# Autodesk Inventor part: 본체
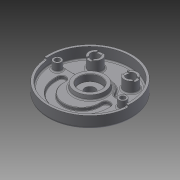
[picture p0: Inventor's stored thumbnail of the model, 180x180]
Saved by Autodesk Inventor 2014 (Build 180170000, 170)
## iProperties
Created: 2015-05
Part Number: 본체
Material: 일반
Document SubType Name: Modeling
Designer: USER
Density: 1 g/cm^3
Appearance: 기본값
Author: USER
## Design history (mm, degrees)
sketch "스케치1"
  geometry: C1 r 95 at (0, 0); 1 further point
  constraints: 1 centre point, 1 coincident
  dimensions: "d0" = 190 diameter of C1
extrude "돌출1" new body sketch "스케치1" distance "d1" = 32; taper "d2" = 0 deg
sketch "스케치2"
  geometry: C1 r 95 at (0, 0) reference; C2 r 90 at (0, 0)
  constraints: 1 centre point, 1 coincident
  dimensions: "d3" = 180 diameter of C2
extrude "돌출2" cut sketch "스케치2" distance "d4" = 25; taper "d5" = 0 deg
sketch "스케치3"
  geometry: C1 r 95 at (0, 0) reference; C2 r 25 at (0, 0)
  constraints: 1 centre point, 1 coincident
  dimensions: "d6" = 50 diameter of C2
extrude "돌출3" join sketch "스케치3" distance "d7" = 12; taper "d8" = -15 deg
sketch "스케치4"
  geometry: L1 (0, 0)-(95, 0); L2 (0, 0)-(94.638, -8.28); L3 (0, 0)-(-94.638, -8.28); C1 r 90 at (0, 0) reference; A1 r 95 centre (0, 0) between (95, 0) and (94.638, -8.28) reference
  constraints: 6 end point, 3 point on circle, 1 horizontal
  dimensions: "d9" = 5 deg angle of L2 L1; "d10" = 170 deg angle of L3 L2
extrude "돌출4" cut sketch "스케치4" distance "d11" = 5; taper "d12" = 0 deg
sketch "스케치5"
  geometry: L1 (-89.196, 12)-(89.196, 12); C1 r 90 at (0, 0) reference; C2 r 42 at (0, 0); A1 r 90 centre (0, 0) between (-89.196, 12) and (89.196, 12) reference
  constraints: 2 end point, 2 point on circle, 1 centre point, 1 coincident, 1 horizontal
  dimensions: "d13" = 84 diameter of C2; "d14" = 12 distance from line of L1 C1.centre
extrude "돌출5" join sketch "스케치5" distance "d15" = 7; taper "d16" = 0 deg
sketch "스케치6"
  geometry: C1 r 35 at (0, 0); A1 r 42 centre (0, 0) between (40.249, 12) and (-40.249, 12) reference
  constraints: 1 centre point, 1 coincident
  dimensions: "d17" = 70 diameter of C1
extrude "돌출6" join sketch "스케치6" distance "d18" = 10; taper "d19" = -10 deg
hole "구멍1" diameter "d22" = 23; stored, may be unused: countersink angle "d26" = 90 deg, drill point angle "d28" = 118 deg; dims "d20" = 10, "d21" = 10, "d23" = 6, "d24" = 50, "d25" = 15, "d27" = 8
sketch "스케치7"
  geometry: C1 r 25 at (0, 0) reference; C2 r 9 at (-74, 0); 1 further point
  constraints: 1 centre point, 1 coincident, 1 horizontal alignment
  dimensions: "d29" = 74 distance of C1.centre point (-74, 0); "d30" = 18 diameter of C2
extrude "돌출7" join sketch "스케치7" distance "d31" = 32; taper "d32" = 0 deg
hole "구멍2" sketch "스케치7" diameter "d33" = 11; stored, may be unused: countersink angle "d37" = 90 deg, drill point angle "d39" = 118 deg; dims "d34" = 6, "d35" = 18, "d36" = 11, "d38" = 8
sketch "스케치8"
  geometry: C1 r 25 at (0, 0) reference; C2 r 15 at (-40, 52); 1 further point
  constraints: 1 centre point, 1 coincident
  dimensions: "d40" = 52 vertical distance of C1.centre point (-40, 52); "d41" = 40 horizontal distance of C1.centre point (-40, 52); "d42" = 30 diameter of C2
extrude "돌출8" join sketch "스케치8" distance "d43" = 32; taper "d44" = 0 deg
hole "구멍3" sketch "스케치8" diameter "d45" = 20; stored, may be unused: countersink angle "d49" = 90 deg, drill point angle "d51" = 118 deg; dims "d46" = 6, "d47" = 18, "d48" = 11, "d50" = 8
sketch "스케치9"
  geometry: L1 (-15, -6)-(15, -6); L2 (15, -6)-(15, 6); L3 (15, 6)-(-15, 6); L4 (-15, 6)-(-15, -6); L5 (-15, -6)-(15, 6); L6 (15, -6)-(-15, 6); C1 r 15 at (0, 0) reference; 1 further point
  constraints: 12 end point, 2 midpoint, 2 parallel, 1 horizontal, 1 perpendicular, 1 tangent
  dimensions: "d52" = 12 distance between parallel lines of L1 L3
extrude "돌출9" cut sketch "스케치9" distance "d53" = 3; taper "d54" = 0 deg
sketch "스케치10"
  geometry: L1 (-6, -15)-(6, -15); L2 (6, -15)-(6, 15); L3 (6, 15)-(-6, 15); L4 (-6, 15)-(-6, -15); L5 (-6, -15)-(6, 15); L6 (6, -15)-(-6, 15); C1 r 15 at (0, 0) reference; 1 further point
  constraints: 12 end point, 2 midpoint, 2 parallel, 1 horizontal, 1 perpendicular, 1 tangent
  dimensions: "d55" = 12 distance of L3.end L2.end
extrude "돌출10" cut sketch "스케치10" distance "d56" = 3; taper "d57" = 0 deg
sketch "스케치11"
  geometry: L1 (-40.249, 12)-(-89.196, 12) reference; L2 (89.196, 12)-(40.249, 12) reference; L3 (-41, -19)-(-59, -19); L4 (41, -19)-(59, -19); L5 (-50, -19)-(-50, -14); L6 (50, -19)-(50, -14); L7 (-41, -19)-(-41, -14); L8 (-59, -14)-(-59, -19); L9 (59, -19)-(59, -14); L10 (41, -19)-(41, -14); A1 r 35 centre (0, 0) between (34.911, 2.5) and (-34.911, 2.5) reference; A2 r 41 centre (0, -19) between (-41, -19) and (41, -19); A3 r 59 centre (0, -19) between (-59, -19) and (59, -19); A4 r 41 centre (0, -19) between (34.911, 2.5) and (26.833, 12); A5 r 41 centre (0, -19) between (-26.833, 12) and (-34.911, 2.5); A6 r 50 centre (0, -19) between (-50, -19) and (50, -19); A7 r 50 centre (0, -19) between (25.426, 24.053) and (-25.426, 24.053); A8 r 9 centre (-50, -14) between (-41, -14) and (-59, -14); A9 r 9 centre (50, -14) between (59, -14) and (41, -14); 2 further points
  constraints: 23 point on circle, 16 end point, 8 centre point, 6 tangent, 4 coincident, 3 point on line, 2 equal length, 2 midpoint, 2 vertical alignment, 1 collinear, 1 perpendicular
  dimensions: "d65" = 59 radius of A3; "d66" = 41 radius of A2; "d71" = 50 radius of A6; "d74" = 19 vertical distance of A6.end A1.centre; "d75" = 5 distance of L5.start L5.end; "d76" = 5 distance of L6.start L6.end; "d77" = 18 diameter of A8; "d78" = 18 diameter of A9
extrude "돌출11" cut sketch "스케치11" distance "d79" = 7; taper "d80" = 0 deg
sketch "스케치12"
  geometry: L1 (0, 0)-(72, 0); L2 (-36.062, -36.062)-(-50.912, -50.912); L3 (36.062, -36.062)-(50.912, -50.912); L4 (0, 0)-(0, -81.693); L5 (-36.062, -36.062)-(0, 0); L6 (36.062, -36.062)-(0, 0); C1 r 95 at (0, 0) reference; A1 r 51 centre (0, 0) between (-36.062, -36.062) and (36.062, -36.062); A2 r 72 centre (0, 0) between (-50.912, -50.912) and (50.912, -50.912)
  constraints: 12 end point, 4 point on circle, 2 centre point, 2 coincident, 2 perpendicular, 1 horizontal, 1 other
  dimensions: "d85" = 72 radius of A2; "d88" = 51 radius of A1; "d89" = 90 deg angle of L3 L2
extrude "돌출12" join sketch "스케치12" distance "d90" = 5; taper "d91" = 0 deg
fillet "모깎기1" dims "d95" = 5
fillet "모깎기2" dims "d96" = 5, "d97" = 3
sketch "스케치15"
  geometry: C1 r 68 at (0, 0); A1 r 67 centre (0, 0) between (-43.709, -50.78) and (43.709, -50.78) reference
  constraints: 1 centre point, 1 coincident, 1 other
  dimensions: "d98" = 136 diameter of C1
feature "엠보싱2" sketch "스케치15" dims "d0" = 190, "d99" = 0.5, "d100" = 0
fillet "모깎기3" dims "d101" = 5
fillet "모깎기4" dims "d102" = 10
fillet "모깎기5" dims "d103" = 3
fillet "모깎기6" dims "d104" = 1
chamfer "모따기1" distance "d105" = 1; stored, may be unused: second distance "d106" = 2, angle "d107" = 45 deg
chamfer "모따기2" distance "d108" = 1; stored, may be unused: second distance "d109" = 2, angle "d110" = 45 deg
fillet "모깎기7" dims "d111" = 3
fillet "모깎기8" dims "d112" = 3
fillet "모깎기9" dims "d113" = 3
fillet "모깎기10" dims "d114" = 0.3
fillet "모깎기11" dims "d115" = 3
node "솔리드1"
mirror "대칭1"
mirror "대칭2"
node "투영된 루프1"
other parameters: "d59" = 118, "d60" = 82, "d81" = 144, "d83" = 45 deg, "d84" = 90 deg
